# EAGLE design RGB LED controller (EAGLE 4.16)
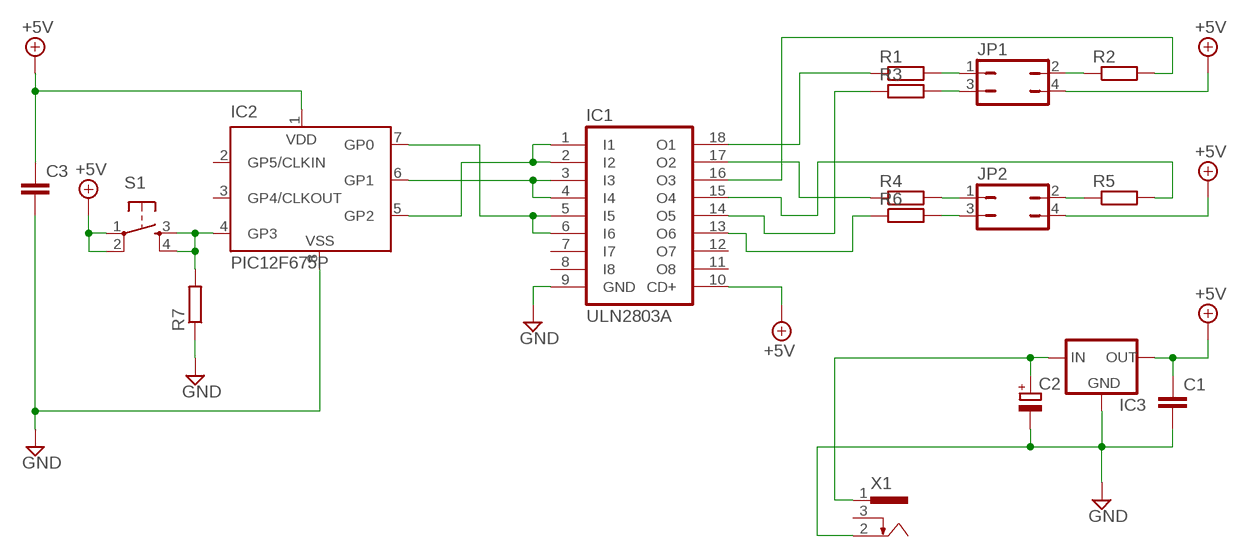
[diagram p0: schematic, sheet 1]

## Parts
C1  C-EU050-025X075  [C050-025X075]
C2  CPOL-EUE2.5-7  [E2,5-7]
C3  C-EU025-024X044  [C025-024X044]
IC1  ULN2803A  [DIL18]
IC2  PIC12F675P  [DIL8]
IC3  V_REG_78XXSIDE  [78XXL]
JP1  JP2Q  [JP2Q]
JP2  JP2Q  [JP2Q]
R1  R-EU_0204/7  [0204/7]
R2  R-EU_0204/7  [0204/7]
R3  R-EU_0204/7  [0204/7]
R4  R-EU_0204/7  [0204/7]
R5  R-EU_0204/7  [0204/7]
R6  R-EU_0204/7  [0204/7]
R7  R-EU_0204/7  [0204/7]
S1  TAC_SWITCHPTH  [TACTILE-PTH]
X1  733980-62  [733980-62]

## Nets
+5V: C1.1 C3.1 IC1.10(CD+) IC2.1(VDD) IC3.OUT JP1.4 JP2.4 S1.1 S1.2
GND: C1.2 C2.- C3.2 IC1.9(GND) IC2.8(VSS) IC3.GND R7.1 X1.2
N$1: JP1.1 R1.2
N$2: JP1.3 R3.2
N$3: JP1.2 R2.1
N$4: IC1.18(O1) R1.1
N$5: IC1.3(I3) IC1.4(I4) IC2.6(GP1)
N$6: IC1.16(O3) R2.2
N$7: IC1.14(O5) R3.1
N$8: IC1.17(O2) R4.1
N$9: JP2.1 R4.2
N$10: JP2.2 R5.1
N$11: IC1.15(O4) R5.2
N$12: JP2.3 R6.2
N$13: IC1.13(O6) R6.1
N$14: IC1.1(I1) IC1.2(I2) IC2.5(GP2)
N$15: IC1.5(I5) IC1.6(I6) IC2.7(GP0)
N$17: IC2.4(GP3) R7.2 S1.3 S1.4
N$26: C2.+ IC3.IN X1.1
Unconnected: IC1.7(I7) IC1.8(I8) IC1.11(O8) IC1.12(O7) IC2.2(GP5/CLKIN) IC2.3(GP4/CLKOUT) X1.3

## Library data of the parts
C1 C3 = rcl:C-EU: CAPACITOR, European symbol
C2 = rcl:CPOL-EU: POLARIZED CAPACITOR, European symbol
IC1 = uln-udn:ULN2803A: DRIVER ARRAY
IC2 = microchip:PIC12F6*: Data Sheet 8-Pin FLASH-Based 8-Bit CMOS Microcontrollers Source: http://www.microchip.com .. 41190c.pdf
IC3 = SparkFunEagle-6-6-07:V_REG_78XX: Voltage Regulator Standard 7805 5V regulator. IGO (Input Ground Output). Spark Fun Electronics SKU : COM-00107
JP1 JP2 = jumper:JP2Q: JUMPER
R1-R7 = rcl:R-EU_: RESISTOR, European symbol
S1 = SparkFunEagle-6-6-07:TAC_SWITCH: Momentary Switch Button commonly used for reset or general input. Spark Fun Electronics SKU : COM-00097
X1 = con-conrad:73398?: FEMALE PRINT CONNECTOR Niedervolt-Steckverbinder Distributor Conrad

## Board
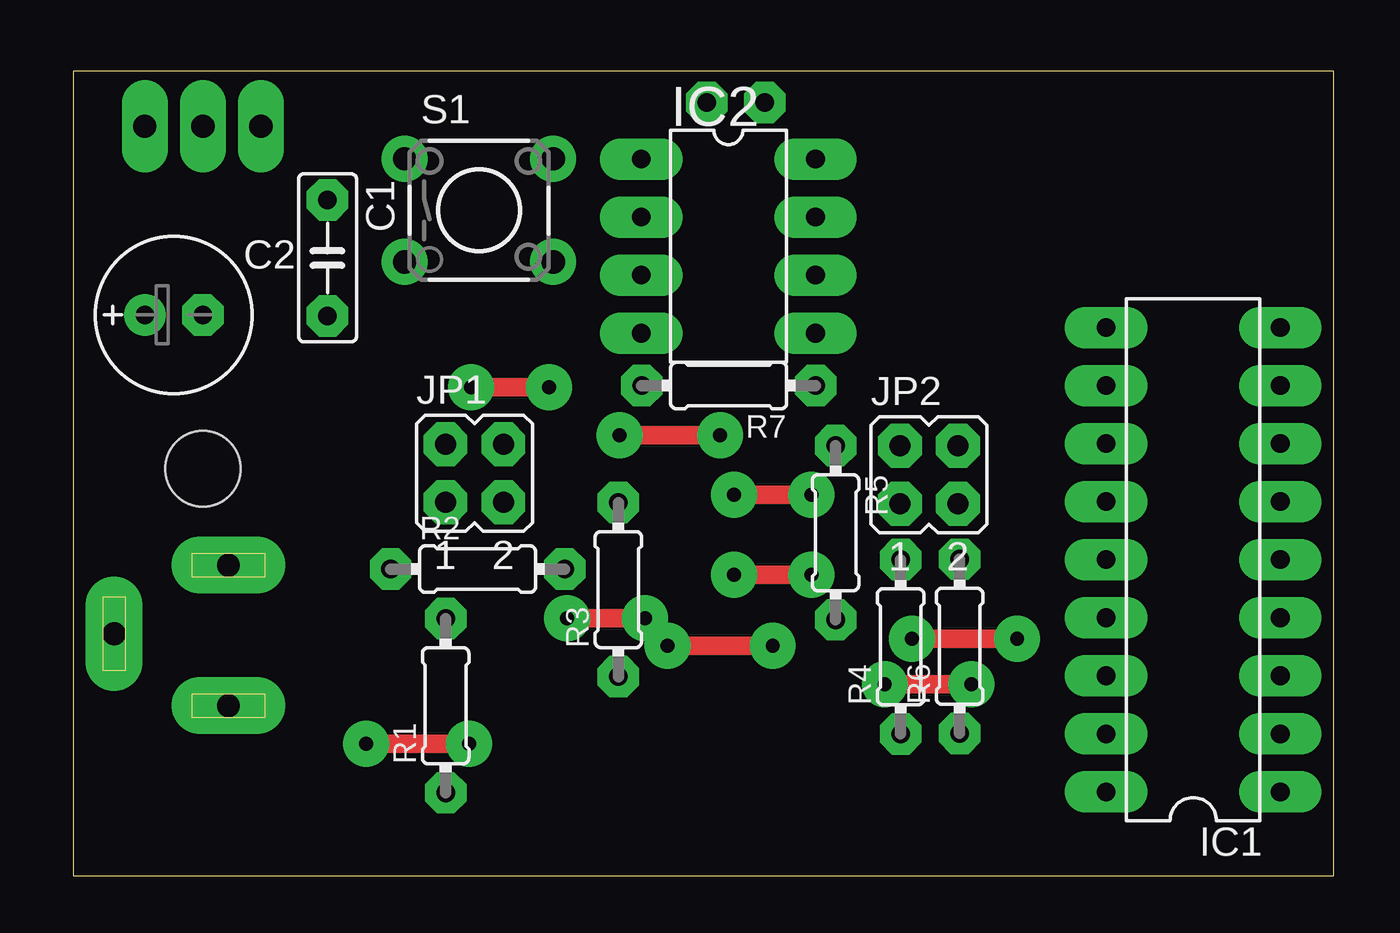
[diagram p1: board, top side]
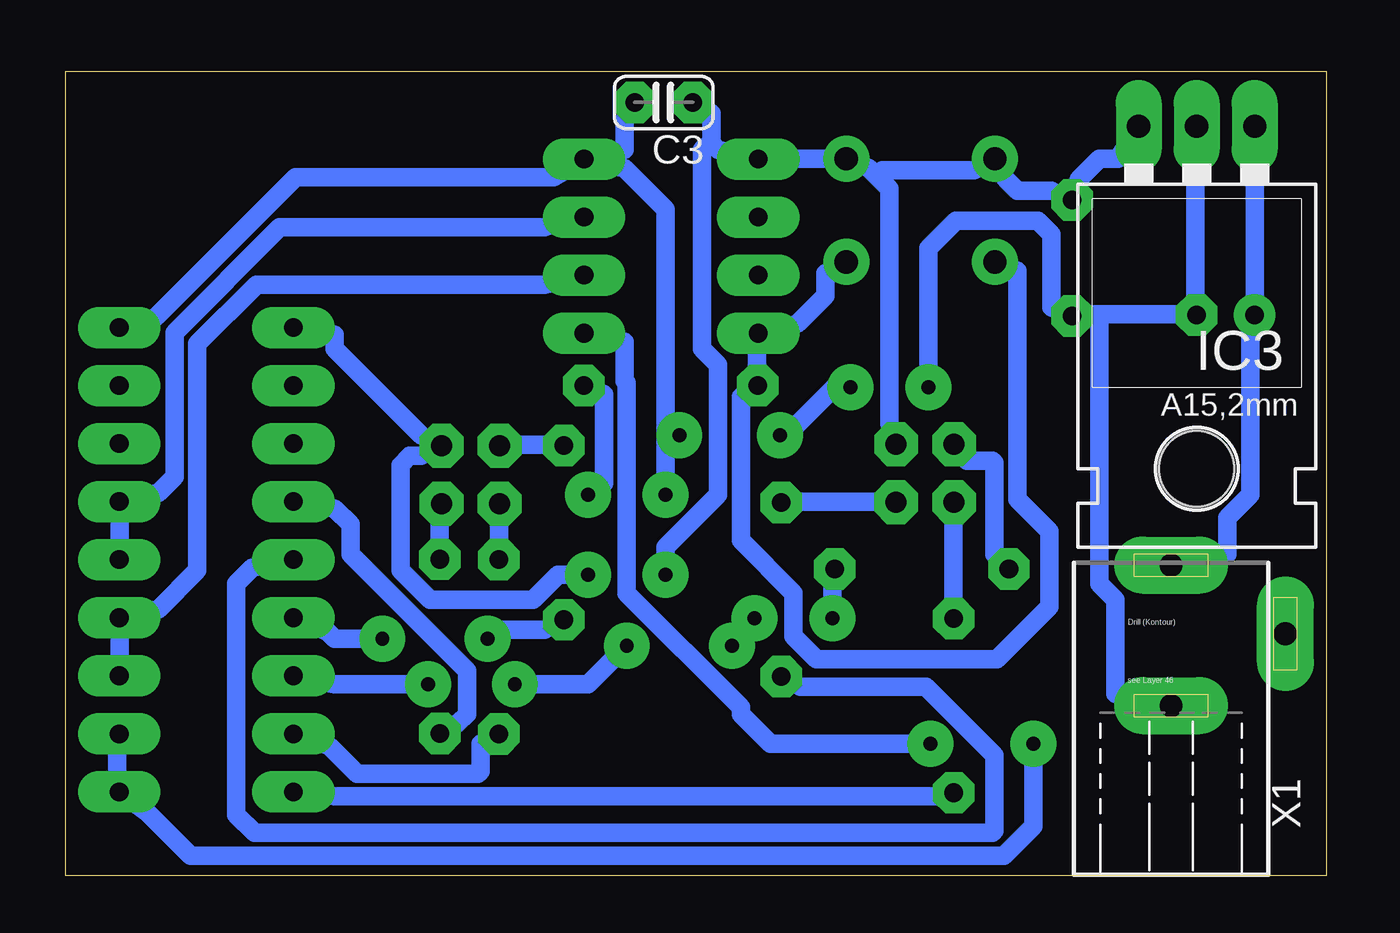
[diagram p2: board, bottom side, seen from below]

Size 55.2 x 35.2 mm. Coordinates in mm from the lower left corner, seen from the top.
Outline: 0,0 55.2,0 55.2,35.2 0,35.2 0,0
Copper layers (1*16): Top 0.8mm / dielectric 1.3mm / Bottom 0.8mm
Design rules "DRC settings smallest": minimum track width 0.8mm, minimum drill 24mil, track to track 0.2mm, track to pad 0.2mm, pad to pad 0.2mm, via to via 0.2mm, smd to smd 8mil, copper to edge 0.3mm, drill to drill 0.3mm, minimum pad ring 0.5mm, minimum via ring 0.7mm, stop-mask expansion 4mil, vias tented up to drill 0mil, thermal gap 10mil
tRestrict: area 1.7,30.7 to 9.5,35.2; area 9.9,28.4 to 12.4,30.8; area 9.9,23.4 to 12.2,25.7; area 4.1,12.2 to 9.5,15.1; area 0.4,8 to 3.3,13.3; area 4,6.1 to 9.4,8.9; area 14.9,14.8 to 20.3,20.3; area 19.8,30.3 to 22.2,32.7; area 19.8,25.6 to 22.2,28.1; area 13.3,30.2 to 15.8,32.6; area 13.2,25.7 to 15.7,28.1; area 26.8,32.4 to 31.4,35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

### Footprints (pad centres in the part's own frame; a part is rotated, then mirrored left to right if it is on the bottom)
C050-025X075 = drill 0.813 octagon: 1 -2.54,0; 2 2.54,0
E2,5-7 = drill 0.813 pad 1.6 round: + -1.27,0 | drill 0.813 pad 1.6 octagon: - 1.27,0
C025-024X044 = drill 0.813 octagon: 1 -1.27,0; 2 1.27,0
DIL18 = drill 0.813 long: 1 -10.16,-3.81; 2 -7.62,-3.81; 3 -5.08,-3.81; 4 -2.54,-3.81; 5 0,-3.81; 6 2.54,-3.81; 7 5.08,-3.81; 8 7.62,-3.81; 9 10.16,-3.81; 10 10.16,3.81; 11 7.62,3.81; 12 5.08,3.81; 13 2.54,3.81; 14 0,3.81; 15 -2.54,3.81; 16 -5.08,3.81; 17 -7.62,3.81; 18 -10.16,3.81
DIL8 = drill 0.813 long: 1 -3.81,-3.81; 2 -1.27,-3.81; 3 1.27,-3.81; 4 3.81,-3.81; 5 3.81,3.81; 6 1.27,3.81; 7 -1.27,3.81; 8 -3.81,3.81
78XXL = drill 1.016 long: GND 0,-3.81; IN -2.54,-3.81; OUT 2.54,-3.81 | hole 3.302: 0,11.176
JP2Q = drill 0.914 octagon: 1 -1.27,-1.27; 2 -1.27,1.27; 3 1.27,-1.27; 4 1.27,1.27
0204/7 = drill 0.813 octagon: 1 -3.81,0; 2 3.81,0
TACTILE-PTH = drill 1.016 round: 1 -3.251,2.261; 2 3.251,2.261; 3 -3.251,-2.261; 4 3.251,-2.261
733980-62 = drill 1 pad 2.5 long: 1 0,8.57; 2 0,2.42; 3 5,5.57

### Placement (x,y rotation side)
C1  11.14,27.04 270 top
C2  4.41,24.54 0 top
C3  29.01,33.84 180 bottom
IC1  49.04,13.83 90 top
IC2  28.69,27.55 270 top
IC3  5.68,28.99 180 bottom
JP1  17.57,17.61 0 top
JP2  37.47,17.55 0 top
R1  16.31,7.44 90 top
R2  17.71,13.42 0 top
R3  23.87,12.52 90 top
R4  36.23,10.02 90 top
R5  33.38,15.01 270 top
R6  38.81,10.04 90 top
R7  28.7,21.45 180 top
S1  17.77,29.12 0 top
X1  6.8,5.02 0 bottom

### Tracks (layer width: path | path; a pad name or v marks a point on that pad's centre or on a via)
+5V  (via drill 0.61)
  Top 0.8: v28.93,13.17 v32.33,13.17
  Bottom 0.8: IC1.10 43.43,23.67 43.43,23.07 39.63,19.27 JP2.4 39.63,18.37 40.13,18.37 40.53,17.97 40.53,13.37 39.23,12.07 34.73,12.07 33.63,13.17 v32.33,13.17 | IC3.OUT 9.13,31.37 9.93,31.37 10.83,30.47 C1.1 12.03,29.97 13.53,29.97 14.03,30.47 S1.1 15.43,30.87 19.43,30.87 19.68,30.62 | 26.93,32.07 26.93,33.37 C3.1 | 26.93,32.07 26.63,31.77 IC2.1 23.13,31.37 21.93,31.37 S1.2 20.03,30.97 19.68,30.62 | 19.68,30.62 19.13,30.07 19.13,19.77 JP1.4 | v28.93,13.17 28.93,14.37 26.63,16.67 26.63,22.37 27.33,23.07 27.33,31.77 27.23,31.87 26.93,32.07
GND  (via drill 0.61)
  Top 0.8: v28.93,16.67 v32.33,16.67 | v17.43,21.37 v20.83,21.37 | v23.93,19.27 v28.33,19.27
  Bottom 0.8: 9.93,24.57 6.53,24.57 C2.- 5.73,25.37 5.73,30.87 IC3.GND | 9.93,24.57 10.33,24.57 C1.2 12.03,24.87 12.03,28.07 12.63,28.67 16.23,28.67 17.43,27.47 v17.43,21.37 | X1.2 9.23,7.97 9.23,12.07 9.93,12.77 9.93,24.57 | IC2.8 30.73,31.77 30.73,33.07 C3.2 | v32.33,16.67 32.13,16.67 31.63,17.17 31.63,21.07 R7.1 | 28.93,19.27 28.93,29.17 30.73,30.97 IC2.8 | 28.93,19.27 v28.93,16.67 | IC1.9 51.23,24.47 45.13,30.57 33.83,30.57 IC2.8 | v20.83,21.37 21.53,21.37 23.63,19.27 v23.93,19.27 | v28.33,19.27 28.93,19.27
N$1
  Bottom 0.8: R1.2 16.33,12.07 16.33,15.47 JP1.1
N$2
  Bottom 0.8: R3.2 23.03,16.37 19.73,16.37 JP1.3
N$3
  Bottom 0.8: R2.1 14.53,14.07 14.53,18.07 14.63,18.17 15.73,18.17 JP1.2
N$4
  Bottom 0.8: R1.1 17.13,3.47 43.43,3.47 IC1.18
N$5
  Bottom 0.8: IC1.3 52.83,9.57 52.83,10.47 IC1.4 51.13,11.67 49.43,13.37 49.43,23.27 46.83,25.87 34.23,25.87 IC2.6
N$6  (via drill 0.61)
  Top 0.8: v35.53,8.37 v39.33,8.37 | v26.03,10.07 v30.63,10.07 | v21.63,11.27 v25.03,11.27
  Bottom 0.8: v39.33,8.37 43.43,8.37 IC1.16 | v35.53,8.37 32.33,8.37 v30.63,10.07 | v26.03,10.07 26.03,10.27 v25.03,11.27 | v21.63,11.27 21.63,12.57 R2.2
N$7
  Bottom 0.8: R3.1 23.03,8.27 17.53,8.27 14.53,5.27 14.53,1.97 14.63,1.87 46.93,1.87 47.73,2.67 47.73,12.77 47.03,13.47 IC1.14
N$8
  Bottom 0.8: R4.1 37.03,5.77 37.03,4.57 37.13,4.47 42.43,4.47 43.63,5.67 IC1.17
N$9
  Bottom 0.8: R4.2 36.23,15.37 JP2.1
N$10
  Bottom 0.8: R5.1 34.23,18.87 35.33,18.87 JP2.2
N$11  (via drill 0.61)
  Top 0.8: v36.73,10.37 v41.33,10.37
  Bottom 0.8: v36.73,10.37 36.33,10.77 34.23,10.77 R5.2 | v41.33,10.37 43.43,10.37 43.73,10.67 IC1.15
N$12
  Bottom 0.8: R6.2 38.83,14.67 38.83,15.37 JP2.3
N$13
  Bottom 0.8: R6.1 38.03,6.67 37.63,7.07 37.63,8.97 42.73,14.07 42.73,15.37 43.43,16.07 IC1.13
N$14  (via drill 0.61)
  Top 0.8: v12.83,5.77 v17.33,5.77
  Bottom 0.8: IC1.2 52.93,5.37 52.93,4.57 IC1.1 51.63,2.77 49.73,0.87 14.13,0.87 12.83,2.17 v12.83,5.77 | v17.33,5.77 24.33,5.77 25.63,7.07 25.63,7.37 30.63,12.37 30.63,21.57 30.73,21.67 30.73,23.37 IC2.5
N$15
  Bottom 0.8: IC2.7 34.23,28.37 45.83,28.37 50.43,23.77 50.43,17.47 51.13,16.77 IC1.6 52.83,15.47 52.83,14.67 IC1.5
N$17
  Bottom 0.8: S1.3 13.53,26.47 13.53,16.47 12.13,15.07 12.13,11.77 14.43,9.47 22.33,9.47 23.33,10.47 23.33,12.37 25.63,14.67 25.63,20.97 R7.2 24.93,22.27 24.93,22.87 IC2.4 23.13,24.17 21.93,25.37 21.93,26.37 S1.4
N$26
  Bottom 0.8: IC3.IN 3.13,30.87 3.13,25.37 C2.+ 3.33,23.67 3.33,16.67 4.33,15.67 4.33,14.07 X1.1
